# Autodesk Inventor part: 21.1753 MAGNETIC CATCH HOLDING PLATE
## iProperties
Created: 2007-03
Part Number: 21.1753 MAGNETIC CATCH HOLDING PLATE
Document SubType Name: Modeling
Designer: Andy Moles
Density: 1 g/cm^3
Author: Andy Moles
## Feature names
1. Extrusion1
2. Hole1
3. Extrusion2
4. Extrusion3
